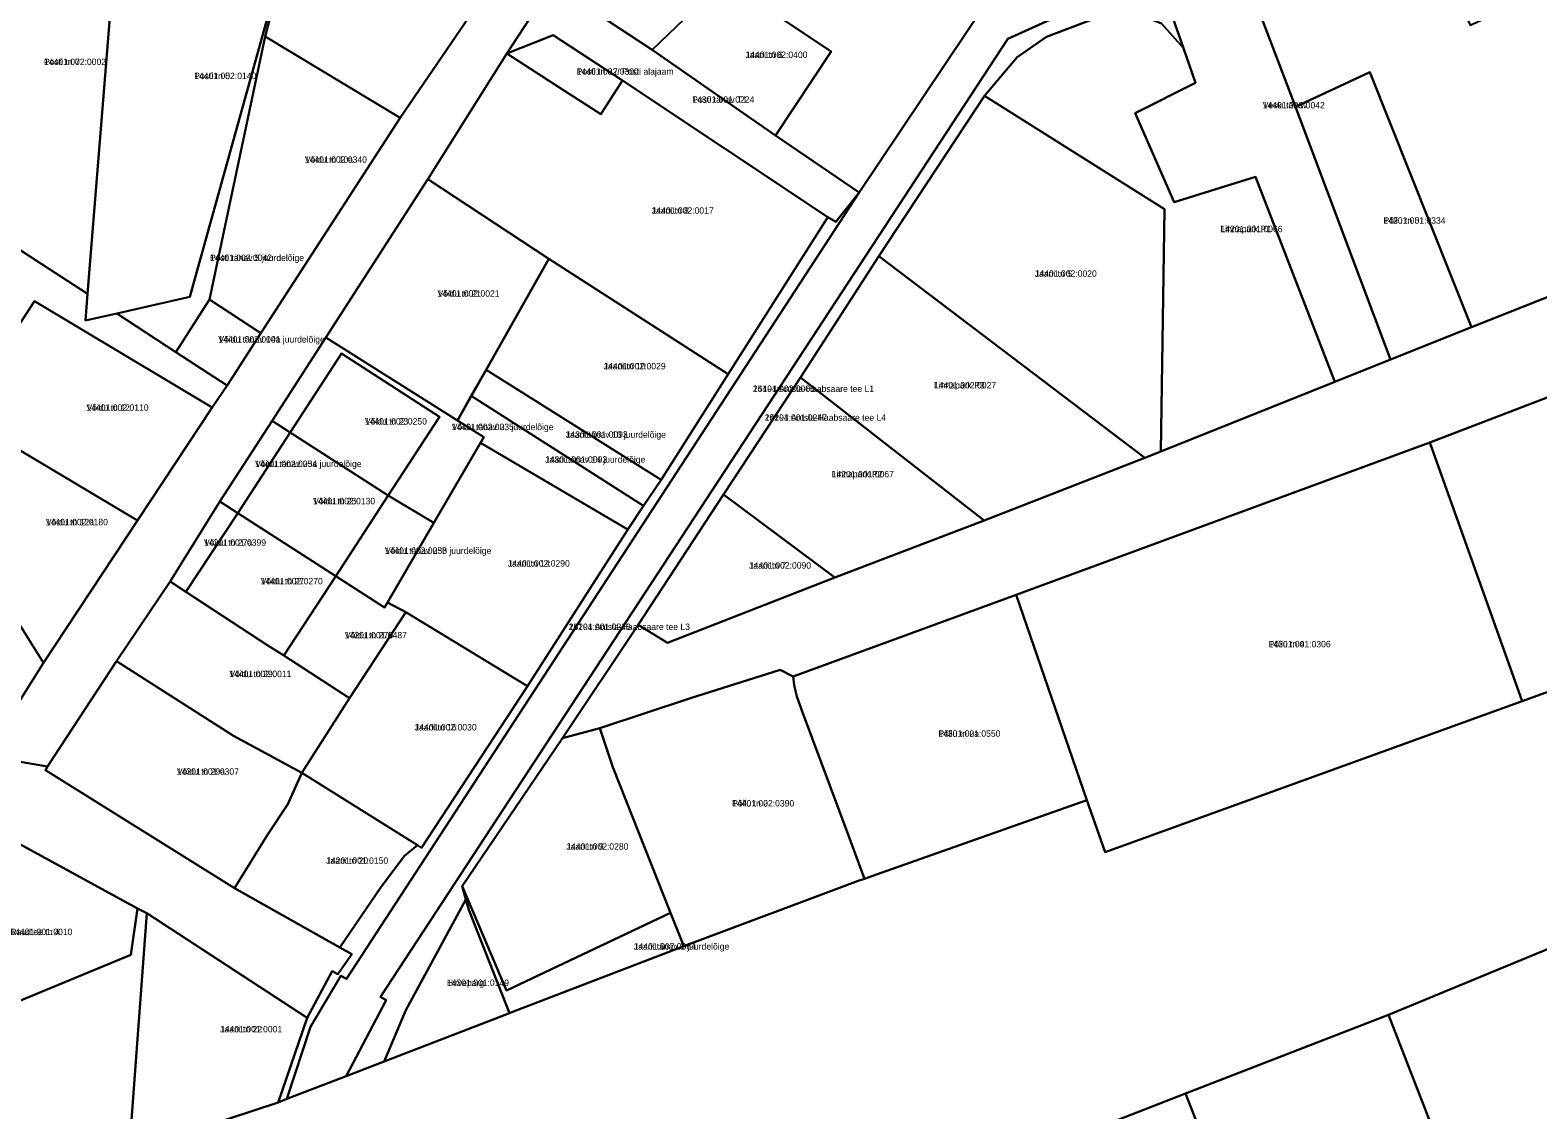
# Model space of a CAD drawing. Extents: x 640657 to 665127, y 6395726 to 6426831.
# Drawn here: x 649927.6 to 650279.7, y 6412244.7 to 6412496.8 of the extents above; entities that cross this region are included whole.
import ezdxf

# ---------------------------------------------------------------- set-up
doc = ezdxf.new("R2010")
doc.units = 0
for name, color, linetype in [('L_AADRESS', 7, 'Continuous'), ('PIIR', 7, 'Continuous'), ('TUNNUS', 7, 'Continuous')]:
    doc.layers.add(name, color=color, linetype=linetype)

msp = doc.modelspace()

# ---------------------------------------------------------------- linework, layer by layer
at = {"layer": 'PIIR'}
for points in [[(650049.5, 6412507.64), (650100.11, 6412586.58), (650110.12, 6412580.5), (650140.41, 6412576.53), (650163.98, 6412575.75), (650166.81, 6412544.84), (650173.59, 6412543.42), (650171.18, 6412533.52), (650121.2, 6412458.89), (650101.64, 6412472.15), (650114.65, 6412491.83), (650089.68, 6412508.43), (650072.85, 6412492.16)], [(649912.56, 6412536.54), (649949, 6412534.42), (649940.97, 6412435.19), (649916.45, 6412451.11), (649915.5, 6412479.78), (649914.89, 6412490.68)], [(650214.58, 6412501.13), (650238.53, 6412511.75), (650254.9, 6412517.39), (650263.87, 6412497.98), (650276.32, 6412503.54), (650269.2, 6412522.44), (650306.65, 6412537.3), (650314.94, 6412516.54), (650319.99, 6412504.57), (650323.98, 6412506.36), (650331.51, 6412487.45), (650289.44, 6412471.02), (650300.92, 6412441.95), (650264.14, 6412427.46), (650240.42, 6412486.98), (650223.07, 6412478.87)], [(649991.28, 6412529.74), (649964.86, 6412434.51), (649947.82, 6412430.62), (649940.46, 6412428.95), (649940.97, 6412435.19), (649949, 6412534.42)], [(649987.48, 6412247.25), (649993.04, 6412264.04), (650000.11, 6412275.95), (650001.42, 6412275.27), (650121.2, 6412458.89), (650171.18, 6412533.52), (650205.18, 6412517.21), (650190.65, 6412510.58), (650155.87, 6412494.77), (650009.35, 6412271.01), (650010.7, 6412270.29), (650001.36, 6412252.53)], [(649947.82, 6412430.62), (649964.86, 6412434.51), (649991.28, 6412529.74), (649982.46, 6412495.27), (649969.45, 6412433.87), (649961.58, 6412421.62)], [(649991.28, 6412529.74), (649996.8, 6412527.89), (650033.45, 6412504.9), (650013.94, 6412476.29), (649982.46, 6412495.27)], [(650190.65, 6412510.58), (650205.18, 6412517.21), (650207.86, 6412518.33), (650209.23, 6412515.05), (650214.58, 6412501.13), (650223.07, 6412478.87), (650245.23, 6412419.87), (650232.23, 6412414.69), (650213.7, 6412462.5), (650194.7, 6412456.6), (650185.6, 6412477.4), (650199.7, 6412484.5), (650196.89, 6412492.57), (650191.7, 6412507.5)], [(650155.87, 6412494.77), (650190.65, 6412510.58), (650191.7, 6412507.5), (650196.89, 6412492.57), (650191.74, 6412498.37), (650186.18, 6412500.59), (650179.5, 6412500.79), (650164.95, 6412495.21), (650158.1, 6412490.46), (650150.4, 6412481.42), (650125.77, 6412443.98), (650107.47, 6412415.68), (650089.5, 6412388.38), (650069.58, 6412357.95), (650051.89, 6412331.42), (650028.46, 6412296.89), (650029.34, 6412293.8), (650015.32, 6412267.89), (650010.22, 6412255.95), (650001.36, 6412252.53), (650010.7, 6412270.29), (650009.35, 6412271.01)], [(650072.85, 6412492.16), (650089.68, 6412508.43), (650114.65, 6412491.83), (650101.64, 6412472.15)], [(650038.91, 6412491.36), (650049.5, 6412507.64), (650072.85, 6412492.16), (650101.64, 6412472.15), (650121.2, 6412458.89), (650115.7, 6412451.99), (650113.86, 6412453.15), (650065.87, 6412485.05), (650049.72, 6412495.59)], [(650150.4, 6412481.42), (650158.1, 6412490.46), (650164.95, 6412495.21), (650179.5, 6412500.79), (650186.18, 6412500.59), (650191.74, 6412498.37), (650196.89, 6412492.57), (650199.7, 6412484.5), (650185.6, 6412477.4), (650194.7, 6412456.6), (650213.7, 6412462.5), (650232.23, 6412414.69), (650191.62, 6412398.42), (650192.44, 6412455.02)], [(649969.45, 6412433.87), (649982.46, 6412495.27), (650013.94, 6412476.29), (649981.43, 6412426.05)], [(650060.81, 6412477.18), (650051.28, 6412483.29), (650038.91, 6412491.36), (650049.72, 6412495.59), (650065.87, 6412485.05)], [(650038.91, 6412491.36), (650051.28, 6412483.29), (650060.81, 6412477.18), (650065.87, 6412485.05), (650113.86, 6412453.15), (650090.59, 6412416.47), (650048.71, 6412443.36), (650020.4, 6412462)], [(650245.23, 6412419.87), (650223.07, 6412478.87), (650240.42, 6412486.98), (650264.14, 6412427.46)], [(649888.39, 6412469.87), (649887.36, 6412478.15), (649915.5, 6412479.78), (649916.45, 6412451.11), (649940.97, 6412435.19), (649940.46, 6412428.95), (649947.82, 6412430.62), (649961.58, 6412421.62), (649973.55, 6412413.79), (649970.1, 6412408.7), (649928.57, 6412433.48), (649911.24, 6412406.94), (649901.45, 6412413.33), (649895.82, 6412404.71), (649892.26, 6412410.82), (649895.71, 6412411.75), (649890.54, 6412450.01), (649856.78, 6412446.02), (649851.44, 6412467.1)], [(650125.77, 6412443.98), (650150.4, 6412481.42), (650192.44, 6412455.02), (650191.62, 6412398.42), (650187.88, 6412396.95)], [(650121.2, 6412458.89), (650001.42, 6412275.27), (650000.11, 6412275.95), (649993.04, 6412264.04), (649987.48, 6412247.25), (649985.44, 6412246.36), (649992.26, 6412266.11), (649998.1, 6412277), (649999.4, 6412276.3), (650002.7, 6412281), (649999.9, 6412282.6), (650009.5, 6412296.7), (650015, 6412304), (650018.04, 6412306.43), (650018.97, 6412305.85), (650043.69, 6412343.56), (650067.14, 6412380.18), (650070.83, 6412385.7), (650074.9, 6412391.8), (650090.59, 6412416.47), (650113.86, 6412453.15), (650115.7, 6412451.99)], [(649996.64, 6412425), (650020.4, 6412462), (650048.71, 6412443.36), (650034.03, 6412417.48), (650027.33, 6412405.66)], [(650034.03, 6412417.48), (650048.71, 6412443.36), (650090.59, 6412416.47), (650074.9, 6412391.8)], [(650107.47, 6412415.68), (650125.77, 6412443.98), (650187.88, 6412396.95), (650150.39, 6412382.24)], [(649952.6, 6412382.3), (649911.24, 6412406.94), (649928.57, 6412433.48), (649970.1, 6412408.7)], [(649969.45, 6412433.87), (649981.43, 6412426.05), (649973.55, 6412413.79), (649961.58, 6412421.62)], [(650254.45, 6412400.46), (650334.61, 6412431.22), (650348.41, 6412393.98), (650398.3, 6412412.03), (650406.48, 6412389.05), (650406.79, 6412388.19), (650338.16, 6412362.55), (650276, 6412340.06), (650275.22, 6412342.26)], [(649996.64, 6412425), (650027.33, 6412405.66), (650033.51, 6412401.75), (650032.7, 6412400.39), (650021.85, 6412381.75), (650011.16, 6412388.1), (650023.12, 6412406.5), (650000.25, 6412421.26), (649988.3, 6412402.84), (649984.1, 6412405.56)], [(650000.25, 6412421.26), (650023.12, 6412406.5), (650011.16, 6412388.1), (649988.3, 6412402.84)], [(650030.56, 6412411.36), (650034.03, 6412417.48), (650074.9, 6412391.8), (650070.83, 6412385.7)], [(649901.45, 6412413.33), (649911.24, 6412406.94), (649952.6, 6412382.3), (649930.7, 6412349), (649895.82, 6412404.71)], [(650089.5, 6412388.38), (650107.47, 6412415.68), (650150.39, 6412382.24), (650115.46, 6412369)], [(649930.7, 6412349), (649917, 6412327.3), (649914.43, 6412323.17), (649894.69, 6412315.18), (649883.22, 6412348.91), (649875.65, 6412369.9), (649863.6, 6412403.34), (649892.26, 6412410.82), (649895.82, 6412404.71)], [(650027.33, 6412405.66), (650030.56, 6412411.36), (650070.83, 6412385.7), (650067.14, 6412380.18), (650032.7, 6412400.39), (650033.51, 6412401.75)], [(649984.1, 6412405.56), (649988.3, 6412402.84), (649976.08, 6412384.01), (649971.86, 6412386.72)], [(649988.3, 6412402.84), (650011.16, 6412388.1), (649998.94, 6412369.3), (649976.08, 6412384.01)], [(650011.02, 6412363.13), (650021.85, 6412381.75), (650032.7, 6412400.39), (650067.14, 6412380.18), (650043.69, 6412343.56), (650015.28, 6412360.87)], [(650174.32, 6412317), (650157.84, 6412364.92), (650254.45, 6412400.46), (650275.22, 6412342.26), (650276, 6412340.06), (650178.58, 6412304.86)], [(650089.5, 6412388.38), (650115.46, 6412369), (650076.42, 6412353.7), (650069.58, 6412357.95)], [(649976.08, 6412384.01), (649963.93, 6412365.6), (649960.23, 6412368.01), (649971.86, 6412386.72)], [(650011.16, 6412388.1), (650021.85, 6412381.75), (650011.02, 6412363.13), (650010.34, 6412361.96), (649998.94, 6412369.3)], [(649976.08, 6412384.01), (649998.94, 6412369.3), (649986.79, 6412350.73), (649983.08, 6412353.12), (649963.93, 6412365.6)], [(649960.23, 6412368.01), (649963.93, 6412365.6), (649983.08, 6412353.12), (649986.79, 6412350.73), (650002.17, 6412340.82), (649990.98, 6412323.38), (649975.03, 6412331.99), (649947.73, 6412349.4)], [(650011.02, 6412363.13), (650015.28, 6412360.87), (650002.17, 6412340.82), (649986.79, 6412350.73), (649998.94, 6412369.3), (650010.34, 6412361.96)], [(650118.67, 6412308.73), (650108.04, 6412337.26), (650106.59, 6412341.14), (650105.96, 6412343.85), (650105.78, 6412345.86), (650157.84, 6412364.92), (650174.32, 6412317), (650125.22, 6412299.63), (650122.39, 6412298.61)], [(650002.17, 6412340.82), (650015.28, 6412360.87), (650043.69, 6412343.56), (650018.97, 6412305.85), (650018.04, 6412306.43), (649990.98, 6412323.38)], [(649931.6, 6412324.8), (649947.73, 6412349.4), (649975.03, 6412331.99), (649990.98, 6412323.38), (649987.7, 6412316), (649983, 6412308.9), (649975.3, 6412296.4), (649931.1, 6412324)], [(650077.1, 6412290.68), (650063.61, 6412324.67), (650060.59, 6412333.82), (650081.77, 6412340.78), (650102.69, 6412347.44), (650105.78, 6412345.86), (650105.96, 6412343.85), (650106.59, 6412341.14), (650108.04, 6412337.26), (650118.67, 6412308.73), (650122.39, 6412298.61), (650120.95, 6412298.12), (650080.24, 6412282.89)], [(650028.46, 6412296.89), (650051.89, 6412331.42), (650060.59, 6412333.82), (650063.61, 6412324.67), (650077.1, 6412290.68), (650038.77, 6412272.49)], [(649990.98, 6412323.38), (650018.04, 6412306.43), (650015, 6412304), (650009.5, 6412296.7), (649999.9, 6412282.6), (649975.3, 6412296.4), (649983, 6412308.9), (649987.7, 6412316)], [(649891.28, 6412301.06), (649915.96, 6412311.64), (649952.59, 6412291.69), (649951.07, 6412280.86), (649898.94, 6412259.26)], [(650028.46, 6412296.89), (650038.77, 6412272.49), (650077.1, 6412290.68), (650080.24, 6412282.89), (650040.46, 6412267.61), (650039.54, 6412267.25), (650030.03, 6412291.38), (650029.34, 6412293.8)], [(650029.34, 6412293.8), (650030.03, 6412291.38), (650039.54, 6412267.25), (650010.22, 6412255.95), (650015.32, 6412267.89)], [(649951.07, 6412280.86), (649952.59, 6412291.69), (649954.77, 6412290.58), (649950.67, 6412234.89), (649874.08, 6412203.09), (649867.77, 6412244.26), (649898.94, 6412259.26)], [(649992.26, 6412266.11), (649985.44, 6412246.36), (649950.67, 6412234.89), (649954.77, 6412290.58)], [(650289.98, 6412285.53), (650315.93, 6412213.55), (650271.65, 6412197.72), (650244.8, 6412266.8)], [(650224.25, 6412178.67), (650212.97, 6412208.68), (650197.41, 6412248.48), (650244.8, 6412266.8), (650271.65, 6412197.72)], [(650212.97, 6412208.68), (650224.25, 6412178.67), (650198.63, 6412167.62), (650171.86, 6412238.52), (650197.41, 6412248.48)]]:
    msp.add_lwpolyline(points, close=True, dxfattribs=at)
for points in [[(649950.67, 6412234.89), (649985.44, 6412246.36), (649987.48, 6412247.25), (650001.36, 6412252.53), (650010.22, 6412255.95), (650039.54, 6412267.25), (650040.46, 6412267.61), (650080.24, 6412282.89), (650120.95, 6412298.12), (650122.39, 6412298.61), (650125.22, 6412299.63), (650174.32, 6412317), (650178.58, 6412304.86), (650276, 6412340.06), (650338.16, 6412362.55), (650406.79, 6412388.19), (650455.36, 6412406.36), (650476.13, 6412414.32), (650520.84, 6412431.45), (650516.48, 6412441.61), (650531.9, 6412455.81), (650578.16, 6412498.39), (650590.01, 6412509.3), (650626.82, 6412523.64)], [(650049.5, 6412507.64), (650038.91, 6412491.36), (650020.4, 6412462), (649996.64, 6412425), (649984.1, 6412405.56), (649971.86, 6412386.72), (649960.23, 6412368.01), (649947.73, 6412349.4), (649931.6, 6412324.8), (649917, 6412327.3), (649930.7, 6412349), (649952.6, 6412382.3), (649970.1, 6412408.7), (649973.55, 6412413.79), (649981.43, 6412426.05), (650013.94, 6412476.29), (650033.45, 6412504.9)], [(650334.61, 6412431.22), (650254.45, 6412400.46), (650157.84, 6412364.92), (650105.78, 6412345.86), (650102.69, 6412347.44), (650081.77, 6412340.78), (650060.59, 6412333.82), (650051.89, 6412331.42), (650069.58, 6412357.95), (650076.42, 6412353.7), (650115.46, 6412369), (650150.39, 6412382.24), (650187.88, 6412396.95), (650191.62, 6412398.42), (650232.23, 6412414.69), (650245.23, 6412419.87), (650264.14, 6412427.46), (650300.92, 6412441.95)], [(650601.5, 6412391.05), (650565.08, 6412376.8), (650522.28, 6412360.19), (650516.03, 6412375.62), (650507.43, 6412372.34), (650490.46, 6412365.12), (650467.47, 6412354.87), (650465.77, 6412354.2), (650435.19, 6412342.1), (650421.06, 6412336.9), (650375.33, 6412320.01), (650371.39, 6412318.51), (650326.13, 6412300.58), (650289.98, 6412285.53), (650244.8, 6412266.8), (650197.41, 6412248.48), (650171.86, 6412238.52)], [(649917, 6412327.3), (649931.6, 6412324.8), (649931.1, 6412324), (649975.3, 6412296.4), (649999.9, 6412282.6), (650002.7, 6412281), (649999.4, 6412276.3), (649998.1, 6412277), (649992.26, 6412266.11), (649954.77, 6412290.58), (649952.59, 6412291.69), (649915.96, 6412311.64)]]:
    msp.add_lwpolyline(points, dxfattribs=at)

# ---------------------------------------------------------------- texts
at = {"layer": 'L_AADRESS'}
for s, p in [('Jaani tn 6', (650094.59, 6412490.29)), ('Posti tn 7', (649930.78, 6412488.64)), ('Posti tn 5', (649965.87, 6412485.35)), ('Posti tn 3 // Posti alajaam', (650055.18, 6412486.38)), ('Posti tänav T1', (650082.18, 6412479.82)), ('Veski tänav', (650215.41, 6412478.51)), ('Võidu tn 10a', (649991.7, 6412465.81)), ('Jaani tn 8', (650072.69, 6412453.91)), ('Põllu tn 5', (650243.61, 6412451.59)), ('Linnapark P1', (650205.53, 6412449.61)), ('Posti tänav 5 juurdelõige', (649969.55, 6412442.88)), ('Jaani tn 5', (650162.16, 6412439.19)), ('Võidu tn 21', (650022.68, 6412434.55)), ('Võidu tänav 10a juurdelõige', (649971.5, 6412423.83)), ('Jaani tn 10', (650061.47, 6412417.58)), ('25194 Antsla-Haabsaare tee L1', (650096.33, 6412412.3)), ('Linnapark P3', (650138.65, 6412413.11)), ('Võidu tn 12', (649940.71, 6412407.89)), ('Võidu tn 23', (650005.72, 6412404.68)), ('25194 Antsla-Haabsaare tee L4', (650099.12, 6412405.56)), ('Võidu tänav 23 juurdelõige', (650026.02, 6412403.38)), ('Jaani tänav 10 juurdelõige', (650052.61, 6412401.59)), ('Võidu tänav 25a juurdelõige', (649980.08, 6412394.77)), ('Jaani tänav 14 juurdelõige', (650047.8, 6412395.77)), ('Linnapark P2', (650114.77, 6412392.34)), ('Võidu tn 25', (649993.63, 6412386.07)), ('Võidu tn 12a', (649931.21, 6412381.16)), ('Võidu tn 27a', (649968.15, 6412376.38)), ('Võidu tänav 25b juurdelõige', (650010.39, 6412374.49)), ('Jaani tn 14', (650039.08, 6412371.51)), ('Jaani tn 7', (650095.44, 6412371.04)), ('Võidu tn 27', (649981.39, 6412367.37)), ('25194 Antsla-Haabsaare tee L3', (650053.32, 6412356.71)), ('Võidu tn 27b', (650001.04, 6412354.75)), ('Põllu tn 4', (650216.78, 6412352.66)), ('Võidu tn 29', (649974.07, 6412345.7)), ('Jaani tn 16', (650017.33, 6412333.24)), ('Põllu tn 2a', (650139.66, 6412331.77)), ('Võidu tn 29a', (649961.81, 6412322.9)), ('Põllu tn 2', (650091.49, 6412315.49)), ('Jaani tn 20', (649996.67, 6412302.11)), ('Jaani tn 9', (650052.78, 6412305.4)), ('Raudtee tn 4', (649922.93, 6412285.45)), ('Jaani tänav 9 juurdelõige', (650068.53, 6412282.07)), ('Hirvepargi', (650024.88, 6412273.58)), ('Jaani tn 22', (649971.91, 6412262.74))]:
    msp.add_text(s, height=1.5, dxfattribs=at).set_placement(p)
at = {"layer": 'TUNNUS'}
for s, p in [('14401:002:0400', (650094.59, 6412490.29)), ('14401:002:0002', (649930.78, 6412488.64)), ('14401:002:0140', (649965.87, 6412485.35)), ('14401:002:0300', (650055.18, 6412486.38)), ('14301:001:0224', (650082.18, 6412479.82)), ('14401:003:0042', (650215.41, 6412478.51)), ('14401:002:0340', (649991.7, 6412465.81)), ('14401:002:0017', (650072.69, 6412453.91)), ('14201:001:0334', (650243.61, 6412451.59)), ('14201:001:0066', (650205.53, 6412449.61)), ('14401:002:0042', (649969.55, 6412442.88)), ('14401:002:0020', (650162.16, 6412439.19)), ('14401:002:0021', (650022.68, 6412434.55)), ('14401:002:0041', (649971.5, 6412423.83)), ('14401:002:0029', (650061.47, 6412417.58)), ('14401:002:0005', (650096.33, 6412412.3)), ('14401:002:0027', (650138.65, 6412413.11)), ('14401:002:0110', (649940.71, 6412407.89)), ('14401:002:0250', (650005.72, 6412404.68)), ('14201:001:0247', (650099.12, 6412405.56)), ('14401:002:0035', (650026.02, 6412403.38)), ('14301:001:0093', (650052.61, 6412401.59)), ('14401:002:0034', (649980.08, 6412394.77)), ('14301:001:0092', (650047.8, 6412395.77)), ('14201:001:0067', (650114.77, 6412392.34)), ('14401:002:0130', (649993.63, 6412386.07)), ('14401:002:0180', (649931.21, 6412381.16)), ('14201:001:0399', (649968.15, 6412376.38)), ('14401:002:0033', (650010.39, 6412374.49)), ('14401:002:0290', (650039.08, 6412371.51)), ('14401:002:0090', (650095.44, 6412371.04)), ('14401:002:0270', (649981.39, 6412367.37)), ('14201:001:0246', (650053.32, 6412356.71)), ('14201:001:0487', (650001.04, 6412354.75)), ('14301:001:0306', (650216.78, 6412352.66)), ('14401:002:0011', (649974.07, 6412345.7)), ('14401:002:0030', (650017.33, 6412333.24)), ('14301:001:0550', (650139.66, 6412331.77)), ('14301:001:0307', (649961.81, 6412322.9)), ('14401:002:0390', (650091.49, 6412315.49)), ('14401:002:0280', (650052.78, 6412305.4)), ('14201:001:0150', (649996.67, 6412302.11)), ('14401:001:0010', (649922.93, 6412285.45)), ('14401:007:0064', (650068.53, 6412282.07)), ('14201:001:0149', (650024.88, 6412273.58)), ('14401:001:0001', (649971.91, 6412262.74))]:
    msp.add_text(s, height=1.5, dxfattribs=at).set_placement(p)

doc.saveas('drawing.dxf')
